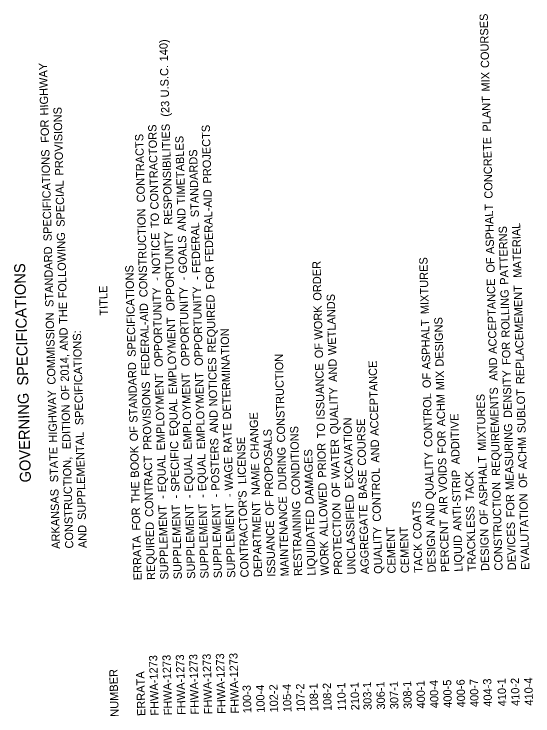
# Model space of a CAD drawing. Extents: x 1929542 to 1931706, y 595440 to 597808.
# Drawn here: x 1929542 to 1929920, y 596392 to 596904 of the extents above; entities that cross this region are included whole.
import ezdxf

# ---------------------------------------------------------------- set-up
doc = ezdxf.new("R2010")
doc.units = 0
doc.layers.add('Default', color=7, linetype='Continuous')

msp = doc.modelspace()

# ---------------------------------------------------------------- texts
at = {"layer": 'Default'}
for s, height, p in [(' COURSES', 6, (1929888.44, 596862.19)), (' 140)', 6, (1929654.23, 596867.03)), (' HIGHWAY', 6, (1929567.02, 596827.59)), (' U.S.C.', 6, (1929654.93, 596840.76)), (' MIX', 6, (1929888.9, 596845.02)), (' PLANT', 6, (1929889.68, 596815.85)), (' (23', 6, (1929655.31, 596826.71)), (' PROVISIONS', 6, (1929577.94, 596783.82)), (' FOR', 6, (1929567.55, 596807.69)), (' CONTRACTORS', 6, (1929647.37, 596759.05)), (' RESPONSIBILITIES', 6, (1929657.42, 596747.97)), (' PROJECTS', 6, (1929685.88, 596778.01)), (' CONTRACTS', 6, (1929637.48, 596764.23)), (' TIMETABLES', 6, (1929666.78, 596762.78)), (' CONCRETE', 6, (1929891, 596766.94)), (' SPECIFICATIONS', 6, (1929569.48, 596735.95)), (' STANDARDS', 6, (1929676.78, 596753.39)), (' SPECIAL', 6, (1929578.95, 596746.39)), (' FEDERAL-AID', 6, (1929687.41, 596720.72)), (' ASPHALT', 6, (1929892.08, 596726.58)), (' CONSTRUCTION', 6, (1929639.34, 596695.08)), (' AND', 6, (1929667.3, 596743.21)), (' TO', 6, (1929647.74, 596745.46)), (' FEDERAL', 6, (1929677.88, 596712.7)), (' MATERIAL', 6, (1929912.05, 596709.32)), (' OPPORTUNITY', 6, (1929659.11, 596685.17)), (' PATTERNS', 6, (1929902.44, 596704.19)), (' FOLLOWING', 6, (1929580.35, 596694.3)), (' NOTICE', 6, (1929648.64, 596711.92)), (' GOALS', 6, (1929668.13, 596712.44)), (' STANDARD', 6, (1929570.76, 596687.97)), (' MIXTURES', 6, (1929844.49, 596682.8)), (' OF', 6, (1929892.45, 596713)), (' SPECIFICATIONS', 8, (1929552.41, 596629.96)), (' SPECIFICATIONS', 6, (1929630.75, 596651.61)), (' FOR', 6, (1929687.95, 596700.81)), (' ORDER', 6, (1929766.2, 596692.57)), (' -', 6, (1929648.77, 596707.06)), (' -', 6, (1929668.26, 596707.59)), (' -', 6, (1929678.01, 596707.85)), (' ACCEPTANCE', 6, (1929894.03, 596653.84)), ('TITLE', 6, (1929610.37, 596683.93)), (' OPPORTUNITY', 6, (1929650.45, 596644.27)), (' OPPORTUNITY', 6, (1929669.95, 596644.79)), (' OPPORTUNITY', 6, (1929679.69, 596645.05)), (' REPLACEMEMENT', 6, (1929914.13, 596631.72)), (' REQUIRED', 6, (1929689.19, 596654.7)), (' WETLANDS', 6, (1929777.02, 596652.9)), (' ROLLING', 6, (1929903.47, 596665.6)), (' THE', 6, (1929580.85, 596675.66)), (' FEDERAL-AID', 6, (1929640.87, 596637.78)), (' WORK', 6, (1929766.96, 596664.19)), (' COMMISSION', 6, (1929572.28, 596631.38)), (' EMPLOYMENT', 6, (1929660.74, 596624.34)), (' ASPHALT', 6, (1929845.57, 596642.45)), (' DESIGNS', 6, (1929855.27, 596644.46)), (' AND', 6, (1929581.37, 596656.09)), (' DETERMINATION', 6, (1929700.25, 596606.02)), (' SPECIFICATIONS:', 6, (1929592.58, 596601.85)), (' OF', 6, (1929767.32, 596650.61)), (' FOR', 6, (1929904.01, 596645.7)), (' 2014,', 6, (1929581.98, 596633.54)), (' NOTICES', 6, (1929690.24, 596615.56)), (' CONSTRUCTION', 6, (1929739.71, 596589.25)), (' AND', 6, (1929894.56, 596634.26)), (' STANDARD', 6, (1929632.04, 596603.63)), (' ISSUANCE', 6, (1929768.53, 596605.88)), (' AND', 6, (1929777.54, 596633.33)), (' ACCEPTANCE', 6, (1929807.86, 596594.05)), (' EMPLOYMENT', 6, (1929681.33, 596584.22)), (' MIX', 6, (1929855.73, 596627.29)), (' DENSITY', 6, (1929905.04, 596607.11)), (' EMPLOYMENT', 6, (1929652.09, 596583.43)), (' EMPLOYMENT', 6, (1929671.58, 596583.96)), (' OF', 6, (1929845.94, 596628.87)), (' OF', 6, (1929582.34, 596619.96)), (' PROVISIONS', 6, (1929642.32, 596583.73)), ('GOVERNING', 8, (1929554.23, 596562.34)), (' HIGHWAY', 6, (1929573.42, 596589.08)), (' QUALITY', 6, (1929778.57, 596595.2)), (' CONTROL', 6, (1929847.09, 596585.86)), (' REQUIREMENTS', 6, (1929896.42, 596564.85)), (' SUBLOT', 6, (1929915.09, 596596.03)), (' EQUAL', 6, (1929661.56, 596593.9)), (' ACHM', 6, (1929856.44, 596600.92)), (' MIXTURES', 6, (1929886.18, 596583.15)), (' EDITION', 6, (1929583.3, 596584.33)), (' AND', 6, (1929690.76, 596595.98)), (' CHANGE', 6, (1929720.53, 596576.98)), (' ADDITIVE', 6, (1929866.94, 596573.25)), (' EXCAVATION', 6, (1929789.38, 596555.71)), (' COURSE', 6, (1929798.69, 596572.3)), (' OF', 6, (1929632.4, 596590.05)), (' RATE', 6, (1929700.9, 596581.79)), (' CONDITIONS', 6, (1929750.5, 596550.85)), (' TO', 6, (1929768.89, 596592.29)), (' MEASURING', 6, (1929906.45, 596554.55)), (' SUPPLEMENTAL', 6, (1929594.44, 596532.75)), (' PROPOSALS', 6, (1929731.02, 596549.56)), (' FOR', 6, (1929856.97, 596581.01)), (' SPECIFIC', 6, (1929662.65, 596553.25)), (' POSTERS', 6, (1929691.89, 596554.04)), (' LICENSE', 6, (1929711.26, 596558.94)), (' WATER', 6, (1929779.44, 596562.73)), (' AND', 6, (1929808.38, 596574.47)), (' ACHM', 6, (1929915.8, 596569.66)), (' STATE', 6, (1929574.19, 596560.19)), (' BOOK', 6, (1929633.11, 596563.52)), (' DURING', 6, (1929740.65, 596554.39)), (' DAMAGES', 6, (1929760.43, 596544.21)), (' PRIOR', 6, (1929769.66, 596563.54)), (' CONTRACT', 6, (1929643.63, 596535.01)), (' EQUAL', 6, (1929652.9, 596552.99)), (' EQUAL', 6, (1929672.4, 596553.51)), (' EQUAL', 6, (1929682.14, 596553.78)), (' WAGE', 6, (1929701.64, 596554.3)), (' QUALITY', 6, (1929848.11, 596547.74)), (' ASPHALT', 6, (1929887.26, 596542.79)), ('           CONSTRUCTION,', 6, (1929585.84, 596489.64)), (' NAME', 6, (1929721.23, 596550.89)), (' VOIDS', 6, (1929857.73, 596553.04)), (' BASE', 6, (1929799.34, 596548.06)), (' CONTROL', 6, (1929809.54, 596531.47)), (' ANTI-STRIP', 6, (1929868.24, 596524.73)), (' TACK', 6, (1929877.4, 596546.9)), (' OF', 6, (1929916.17, 596556.08)), (' THE', 6, (1929633.61, 596544.88)), (' ALLOWED', 6, (1929770.81, 596520.68)), (' OF', 6, (1929779.8, 596549.15)), ('CONSTRUCTION', 6, (1929898.22, 596498.03)), ('           ARKANSAS', 6, (1929576.09, 596489.38)), ("CONTRACTOR'S", 6, (1929713.03, 596493.05)), (' -', 6, (1929653.03, 596548.14)), (' -', 6, (1929662.78, 596548.4)), (' -', 6, (1929672.53, 596548.66)), (' -', 6, (1929682.27, 596548.92)), (' -', 6, (1929692.02, 596549.18)), (' -', 6, (1929701.77, 596549.44)), ('MAINTENANCE', 6, (1929742.27, 596493.84)), ('UNCLASSIFIED', 6, (1929791, 596495.15)), (' AIR', 6, (1929858.16, 596536.86)), (' FOR', 6, (1929906.99, 596534.65)), ('EVALUTATION', 6, (1929917.71, 596498.55)), ('SUPPLEMENT', 6, (1929654.55, 596491.49)), ('SUPPLEMENT', 6, (1929664.3, 596491.75)), ('SUPPLEMENT', 6, (1929674.05, 596492.01)), ('SUPPLEMENT', 6, (1929683.79, 596492.27)), ('SUPPLEMENT', 6, (1929693.54, 596492.53)), ('SUPPLEMENT', 6, (1929703.29, 596492.79)), ('DEPARTMENT', 6, (1929722.78, 596493.32)), (' OF', 6, (1929731.39, 596535.98)), ('RESTRAINING', 6, (1929752.02, 596494.1)), ('PROTECTION', 6, (1929781.26, 596494.89)), ('AGGREGATE', 6, (1929800.75, 596495.41)), (' COATS', 6, (1929839.14, 596518.79)), (' AND', 6, (1929848.64, 596528.17)), (' FOR', 6, (1929634.15, 596524.97)), ('LIQUIDATED', 6, (1929761.77, 596494.36)), ('TRACKLESS', 6, (1929878.72, 596497.5)), (' OF', 6, (1929887.63, 596529.21)), ('PERCENT', 6, (1929859.23, 596496.98)), ('           AND', 6, (1929595.59, 596489.9)), ('REQUIRED', 6, (1929644.81, 596491.22)), ('ISSUANCE', 6, (1929732.53, 596493.58)), ('QUALITY', 6, (1929810.5, 596495.67)), ('CEMENT', 6, (1929829.99, 596496.19)), ('DEVICES', 6, (1929907.96, 596498.29)), ('CEMENT', 6, (1929820.24, 596495.93)), ('DESIGN', 6, (1929849.48, 596496.72)), ('DESIGN', 6, (1929888.47, 596497.76)), ('ERRATA', 6, (1929635.06, 596490.96)), ('WORK', 6, (1929771.51, 596494.62)), ('LIQUID', 6, (1929868.98, 596497.24)), ('TACK', 6, (1929839.74, 596496.46)), ('FHWA-1273', 6, (1929705.94, 596393.87)), ('FHWA-1273', 6, (1929647.46, 596392.3)), ('FHWA-1273', 6, (1929657.21, 596392.56)), ('FHWA-1273', 6, (1929666.96, 596392.82)), ('FHWA-1273', 6, (1929676.7, 596393.08)), ('FHWA-1273', 6, (1929686.45, 596393.34)), ('FHWA-1273', 6, (1929696.2, 596393.6)), ('NUMBER', 6, (1929618.22, 596391.51)), ('ERRATA', 6, (1929637.72, 596392.04)), ('307-1', 6, (1929822.23, 596396.99)), ('308-1', 6, (1929831.97, 596397.25)), ('400-1', 6, (1929841.72, 596397.51)), ('400-4', 6, (1929851.46, 596397.77)), ('400-5', 6, (1929861.21, 596398.03)), ('400-6', 6, (1929870.96, 596398.3)), ('400-7', 6, (1929880.7, 596398.56)), ('404-3', 6, (1929890.45, 596398.82)), ('410-1', 6, (1929900.87, 596399.1)), ('410-2', 6, (1929910.62, 596399.36)), ('410-4', 6, (1929920.36, 596399.62)), ('100-3', 6, (1929715.01, 596394.11)), ('100-4', 6, (1929724.76, 596394.37)), ('102-2', 6, (1929734.51, 596394.63)), ('105-4', 6, (1929744.25, 596394.89)), ('107-2', 6, (1929754, 596395.16)), ('108-1', 6, (1929763.75, 596395.42)), ('108-2', 6, (1929773.49, 596395.68)), ('110-1', 6, (1929783.91, 596395.96)), ('210-1', 6, (1929793.66, 596396.22)), ('303-1', 6, (1929802.73, 596396.46)), ('306-1', 6, (1929812.48, 596396.73))]:
    msp.add_text(s, height=height, rotation=91.5377, dxfattribs=at).set_placement(p)

doc.saveas('drawing.dxf')
